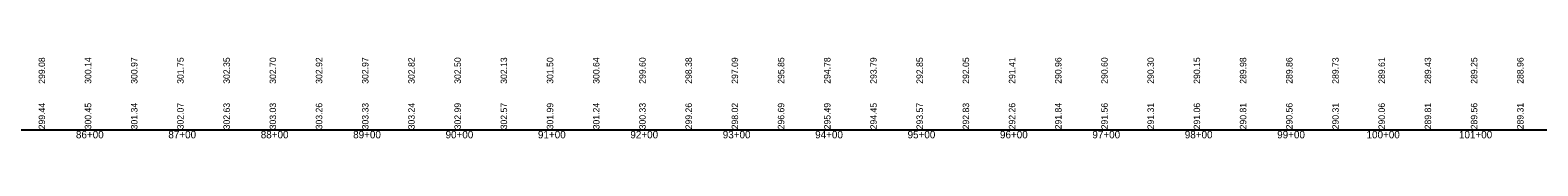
# Model space of a CAD drawing. Extents: x 1876258 to 1926563, y 729739 to 834437.
# Drawn here: x 1886896 to 1888528, y 830495 to 830583 of the extents above; entities that cross this region are included whole.
import ezdxf

# ---------------------------------------------------------------- set-up
doc = ezdxf.new("R2010")
doc.units = 0
for name, color, linetype in [('RD_EX_RailRoad', 7, 'Continuous'), ('RD_PD_ALT3_CL', 7, 'Continuous'), ('RD_PD_Final_Cl', 7, 'Continuous')]:
    doc.layers.add(name, color=color, linetype=linetype)

msp = doc.modelspace()

# ---------------------------------------------------------------- linework, layer by layer
at = {"layer": 'RD_PD_Final_Cl'}
msp.add_line((1878363.1, 830504.3), (1926563.1, 830504.3), dxfattribs=at)

# ---------------------------------------------------------------- texts
at = {"layer": 'RD_EX_RailRoad'}
for s, p in [('299.08', (1886912.1, 830554.3)), ('300.14', (1886962.1, 830554.3)), ('300.97', (1887012.1, 830554.3)), ('301.75', (1887062.1, 830554.3)), ('302.35', (1887112.1, 830554.3)), ('302.70', (1887162.1, 830554.3)), ('302.92', (1887212.1, 830554.3)), ('302.97', (1887262.1, 830554.3)), ('302.82', (1887312.1, 830554.3)), ('302.50', (1887362.1, 830554.3)), ('302.13', (1887412.1, 830554.3)), ('301.50', (1887462.1, 830554.3)), ('300.64', (1887512.1, 830554.3)), ('299.60', (1887562.1, 830554.3)), ('298.38', (1887612.1, 830554.3)), ('297.09', (1887662.1, 830554.3)), ('295.85', (1887712.1, 830554.3)), ('294.78', (1887762.1, 830554.3)), ('293.79', (1887812.1, 830554.3)), ('292.85', (1887862.1, 830554.3)), ('292.05', (1887912.1, 830554.3)), ('291.41', (1887962.1, 830554.3)), ('290.96', (1888012.1, 830554.3)), ('290.60', (1888062.1, 830554.3)), ('290.30', (1888112.1, 830554.3)), ('290.15', (1888162.1, 830554.3)), ('289.98', (1888212.1, 830554.3)), ('289.86', (1888262.1, 830554.3)), ('289.73', (1888312.1, 830554.3)), ('289.61', (1888362.1, 830554.3)), ('289.43', (1888412.1, 830554.3)), ('289.25', (1888462.1, 830554.3)), ('288.96', (1888512.1, 830554.3)), ('299.44', (1886912.1, 830505)), ('300.45', (1886962.1, 830505)), ('301.34', (1887012.1, 830505)), ('302.07', (1887062.1, 830505)), ('302.63', (1887112.1, 830505)), ('303.03', (1887162.1, 830505)), ('303.26', (1887212.1, 830505)), ('303.33', (1887262.1, 830505)), ('303.24', (1887312.1, 830505)), ('302.99', (1887362.1, 830505)), ('302.57', (1887412.1, 830505)), ('301.99', (1887462.1, 830505)), ('301.24', (1887512.1, 830505)), ('300.33', (1887562.1, 830505)), ('299.26', (1887612.1, 830505)), ('298.02', (1887662.1, 830505)), ('296.69', (1887712.1, 830505)), ('295.49', (1887762.1, 830505)), ('294.45', (1887812.1, 830505)), ('293.57', (1887862.1, 830505)), ('292.83', (1887912.1, 830505)), ('292.26', (1887962.1, 830505)), ('291.84', (1888012.1, 830505)), ('291.56', (1888062.1, 830505)), ('291.31', (1888112.1, 830505)), ('291.06', (1888162.1, 830505)), ('290.81', (1888212.1, 830505)), ('290.56', (1888262.1, 830505)), ('290.31', (1888312.1, 830505)), ('290.06', (1888362.1, 830505)), ('289.81', (1888412.1, 830505)), ('289.56', (1888462.1, 830505)), ('289.31', (1888512.1, 830505))]:
    msp.add_text(s, height=7, rotation=90, dxfattribs=at).set_placement(p)
at = {"layer": 'RD_PD_ALT3_CL'}
for s, p in [('86+00', (1886945.5, 830495.3)), ('86+00', (1886945.5, 830495.3)), ('87+00', (1887045.5, 830495.3)), ('87+00', (1887045.5, 830495.3)), ('88+00', (1887145.5, 830495.3)), ('88+00', (1887145.5, 830495.3)), ('89+00', (1887245.5, 830495.3)), ('89+00', (1887245.5, 830495.3)), ('90+00', (1887345.5, 830495.3)), ('90+00', (1887345.5, 830495.3)), ('91+00', (1887445.5, 830495.3)), ('91+00', (1887445.5, 830495.3)), ('92+00', (1887545.5, 830495.3)), ('92+00', (1887545.5, 830495.3)), ('93+00', (1887645.5, 830495.3)), ('93+00', (1887645.5, 830495.3)), ('94+00', (1887745.5, 830495.3)), ('94+00', (1887745.5, 830495.3)), ('95+00', (1887845.5, 830495.3)), ('95+00', (1887845.5, 830495.3)), ('96+00', (1887945.5, 830495.3)), ('96+00', (1887945.5, 830495.3)), ('97+00', (1888045.5, 830495.3)), ('97+00', (1888045.5, 830495.3)), ('98+00', (1888145.5, 830495.3)), ('98+00', (1888145.5, 830495.3)), ('99+00', (1888245.5, 830495.3)), ('99+00', (1888245.5, 830495.3)), ('100+00', (1888342.2, 830495.3)), ('100+00', (1888342.2, 830495.3)), ('101+00', (1888442.2, 830495.3)), ('101+00', (1888442.2, 830495.3))]:
    msp.add_text(s, height=8, dxfattribs=at).set_placement(p)

doc.saveas('drawing.dxf')
